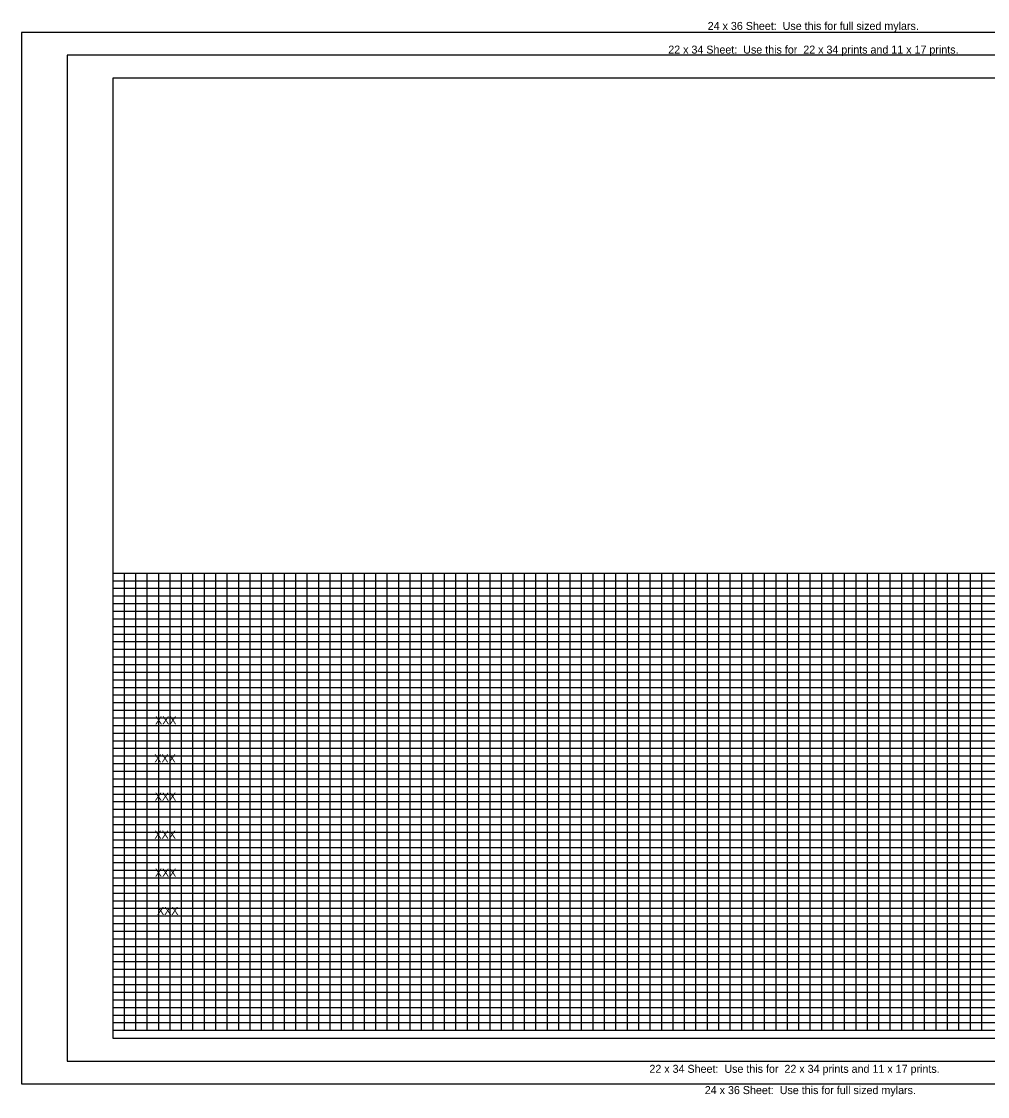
# Model space of a CAD drawing. Extents: x -3549 to -1863, y -2443 to -1503.
# Drawn here: x -3549 to -2704, y -2443 to -1503 of the extents above; entities that cross this region are included whole.
import ezdxf

# ---------------------------------------------------------------- set-up
doc = ezdxf.new("R2010")
doc.units = 0
for name, color, linetype in [('G_BORDER', 7, 'Continuous'), ('G_GRID_MAJOR', 7, 'Continuous'), ('G_GRID_MINOR', 7, 'Continuous'), ('G_SHEET_EDGE', 7, 'Continuous')]:
    doc.layers.add(name, color=color, linetype=linetype)

msp = doc.modelspace()

# ---------------------------------------------------------------- linework, layer by layer
at = {"layer": 'G_BORDER'}
msp.add_lwpolyline([(-2169, -1552.26), (-3469, -1552.26), (-3469, -2392.26), (-2169, -2392.26)], close=True, dxfattribs=at)
at = {"layer": 'G_GRID_MAJOR'}
for p, q in [((-2399, -1985.59), (-3469, -1985.59)), ((-3379, -2385.59), (-3379, -1985.59)), ((-3279, -2385.59), (-3279, -1985.59)), ((-3179, -2385.59), (-3179, -1985.59)), ((-3079, -2385.59), (-3079, -1985.59)), ((-2979, -2385.59), (-2979, -1985.59)), ((-2879, -2385.59), (-2879, -1985.59)), ((-2779, -2385.59), (-2779, -1985.59)), ((-2399, -2018.92), (-3469, -2018.92)), ((-2399, -2052.26), (-3469, -2052.26)), ((-2399, -2085.59), (-3469, -2085.59)), ((-2399, -2118.92), (-3469, -2118.92)), ((-2399, -2152.26), (-3469, -2152.26)), ((-2399, -2185.59), (-3469, -2185.59)), ((-2399, -2218.92), (-3469, -2218.92)), ((-2399, -2252.26), (-3469, -2252.26)), ((-2399, -2285.59), (-3469, -2285.59)), ((-2399, -2318.92), (-3469, -2318.92)), ((-2399, -2352.26), (-3469, -2352.26)), ((-2399, -2385.59), (-3469, -2385.59))]:
    msp.add_line(p, q, dxfattribs=at)
at = {"layer": 'G_GRID_MINOR'}
for p, q in [((-2399, -1992.26), (-3469, -1992.26)), ((-3459, -2385.59), (-3459, -1985.59)), ((-3449, -2385.59), (-3449, -1985.59)), ((-3439, -2385.59), (-3439, -1985.59)), ((-3429, -2385.59), (-3429, -1985.59)), ((-3419, -2385.59), (-3419, -1985.59)), ((-3409, -2385.59), (-3409, -1985.59)), ((-3399, -2385.59), (-3399, -1985.59)), ((-3389, -2385.59), (-3389, -1985.59)), ((-3369, -2385.59), (-3369, -1985.59)), ((-3359, -2385.59), (-3359, -1985.59)), ((-3349, -2385.59), (-3349, -1985.59)), ((-3339, -2385.59), (-3339, -1985.59)), ((-3329, -2385.59), (-3329, -1985.59)), ((-3319, -2385.59), (-3319, -1985.59)), ((-3309, -2385.59), (-3309, -1985.59)), ((-3299, -2385.59), (-3299, -1985.59)), ((-3289, -2385.59), (-3289, -1985.59)), ((-3269, -2385.59), (-3269, -1985.59)), ((-3259, -2385.59), (-3259, -1985.59)), ((-3249, -2385.59), (-3249, -1985.59)), ((-3239, -2385.59), (-3239, -1985.59)), ((-3229, -2385.59), (-3229, -1985.59)), ((-3219, -2385.59), (-3219, -1985.59)), ((-3209, -2385.59), (-3209, -1985.59)), ((-3199, -2385.59), (-3199, -1985.59)), ((-3189, -2385.59), (-3189, -1985.59)), ((-3169, -2385.59), (-3169, -1985.59)), ((-3159, -2385.59), (-3159, -1985.59)), ((-3149, -2385.59), (-3149, -1985.59)), ((-3139, -2385.59), (-3139, -1985.59)), ((-3129, -2385.59), (-3129, -1985.59)), ((-3119, -2385.59), (-3119, -1985.59)), ((-3109, -2385.59), (-3109, -1985.59)), ((-3099, -2385.59), (-3099, -1985.59)), ((-3089, -2385.59), (-3089, -1985.59)), ((-3069, -2385.59), (-3069, -1985.59)), ((-3059, -2385.59), (-3059, -1985.59)), ((-3049, -2385.59), (-3049, -1985.59)), ((-3039, -2385.59), (-3039, -1985.59)), ((-3029, -2385.59), (-3029, -1985.59)), ((-3019, -2385.59), (-3019, -1985.59)), ((-3009, -2385.59), (-3009, -1985.59)), ((-2999, -2385.59), (-2999, -1985.59)), ((-2989, -2385.59), (-2989, -1985.59)), ((-2969, -2385.59), (-2969, -1985.59)), ((-2959, -2385.59), (-2959, -1985.59)), ((-2949, -2385.59), (-2949, -1985.59)), ((-2939, -2385.59), (-2939, -1985.59)), ((-2929, -2385.59), (-2929, -1985.59)), ((-2919, -2385.59), (-2919, -1985.59)), ((-2909, -2385.59), (-2909, -1985.59)), ((-2899, -2385.59), (-2899, -1985.59)), ((-2889, -2385.59), (-2889, -1985.59)), ((-2869, -2385.59), (-2869, -1985.59)), ((-2859, -2385.59), (-2859, -1985.59)), ((-2849, -2385.59), (-2849, -1985.59)), ((-2839, -2385.59), (-2839, -1985.59)), ((-2829, -2385.59), (-2829, -1985.59)), ((-2819, -2385.59), (-2819, -1985.59)), ((-2809, -2385.59), (-2809, -1985.59)), ((-2799, -2385.59), (-2799, -1985.59)), ((-2789, -2385.59), (-2789, -1985.59)), ((-2769, -2385.59), (-2769, -1985.59)), ((-2759, -2385.59), (-2759, -1985.59)), ((-2749, -2385.59), (-2749, -1985.59)), ((-2739, -2385.59), (-2739, -1985.59)), ((-2729, -2385.59), (-2729, -1985.59)), ((-2719, -2385.59), (-2719, -1985.59)), ((-2709, -2385.59), (-2709, -1985.59)), ((-2399, -1998.92), (-3469, -1998.92)), ((-2399, -2005.59), (-3469, -2005.59)), ((-2399, -2012.26), (-3469, -2012.26)), ((-2399, -2025.59), (-3469, -2025.59)), ((-2399, -2032.26), (-3469, -2032.26)), ((-2399, -2038.92), (-3469, -2038.92)), ((-2399, -2045.59), (-3469, -2045.59)), ((-2399, -2058.92), (-3469, -2058.92)), ((-2399, -2065.59), (-3469, -2065.59)), ((-2399, -2072.26), (-3469, -2072.26)), ((-2399, -2078.92), (-3469, -2078.92)), ((-2399, -2092.26), (-3469, -2092.26)), ((-2399, -2098.92), (-3469, -2098.92)), ((-2399, -2105.59), (-3469, -2105.59)), ((-2399, -2112.26), (-3469, -2112.26)), ((-2399, -2125.59), (-3469, -2125.59)), ((-2399, -2132.26), (-3469, -2132.26)), ((-2399, -2138.92), (-3469, -2138.92)), ((-2399, -2145.59), (-3469, -2145.59)), ((-2399, -2158.92), (-3469, -2158.92)), ((-2399, -2165.59), (-3469, -2165.59)), ((-2399, -2172.26), (-3469, -2172.26)), ((-2399, -2178.92), (-3469, -2178.92)), ((-2399, -2192.26), (-3469, -2192.26)), ((-2399, -2198.92), (-3469, -2198.92)), ((-2399, -2205.59), (-3469, -2205.59)), ((-2399, -2212.26), (-3469, -2212.26)), ((-2399, -2225.59), (-3469, -2225.59)), ((-2399, -2232.26), (-3469, -2232.26)), ((-2399, -2238.92), (-3469, -2238.92)), ((-2399, -2245.59), (-3469, -2245.59)), ((-2399, -2258.92), (-3469, -2258.92)), ((-2399, -2265.59), (-3469, -2265.59)), ((-2399, -2272.26), (-3469, -2272.26)), ((-2399, -2278.92), (-3469, -2278.92)), ((-2399, -2292.26), (-3469, -2292.26)), ((-2399, -2298.92), (-3469, -2298.92)), ((-2399, -2305.59), (-3469, -2305.59)), ((-2399, -2312.26), (-3469, -2312.26)), ((-2399, -2325.59), (-3469, -2325.59)), ((-2399, -2332.26), (-3469, -2332.26)), ((-2399, -2338.92), (-3469, -2338.92)), ((-2399, -2345.59), (-3469, -2345.59)), ((-2399, -2358.92), (-3469, -2358.92)), ((-2399, -2365.59), (-3469, -2365.59)), ((-2399, -2372.26), (-3469, -2372.26)), ((-2399, -2378.92), (-3469, -2378.92))]:
    msp.add_line(p, q, dxfattribs=at)
at = {"layer": 'G_SHEET_EDGE'}
for points in [[(-2129, -1512.26), (-3549, -1512.26), (-3549, -2432.26), (-2129, -2432.26)], [(-2149, -1532.26), (-3509, -1532.26), (-3509, -2412.26), (-2149, -2412.26)]]:
    msp.add_lwpolyline(points, close=True, dxfattribs=at)

# ---------------------------------------------------------------- texts
at = {"layer": 'G_GRID_MAJOR'}
for p in [(-3432.16, -2117.67), (-3432.87, -2151.01), (-3432.44, -2184.34), (-3432.73, -2217.67), (-3432.3, -2251.01), (-3430.45, -2284.34)]:
    msp.add_text('XXX', height=7, dxfattribs=at).set_placement(p)
at = {"layer": 'G_SHEET_EDGE'}
for s, p in [('24 x 36 Sheet:  Use this for full sized mylars. ', (-2948.75, -1510.04)), ('22 x 34 Sheet:  Use this for  22 x 34 prints and 11 x 17 prints. ', (-2983.25, -1530.76)), ('22 x 34 Sheet:  Use this for  22 x 34 prints and 11 x 17 prints. ', (-2999.74, -2422.56)), ('24 x 36 Sheet:  Use this for full sized mylars. ', (-2951.31, -2441.17))]:
    msp.add_text(s, height=7, dxfattribs=at).set_placement(p)

doc.saveas('drawing.dxf')
